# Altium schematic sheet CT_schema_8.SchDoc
size 252 x 159 mm
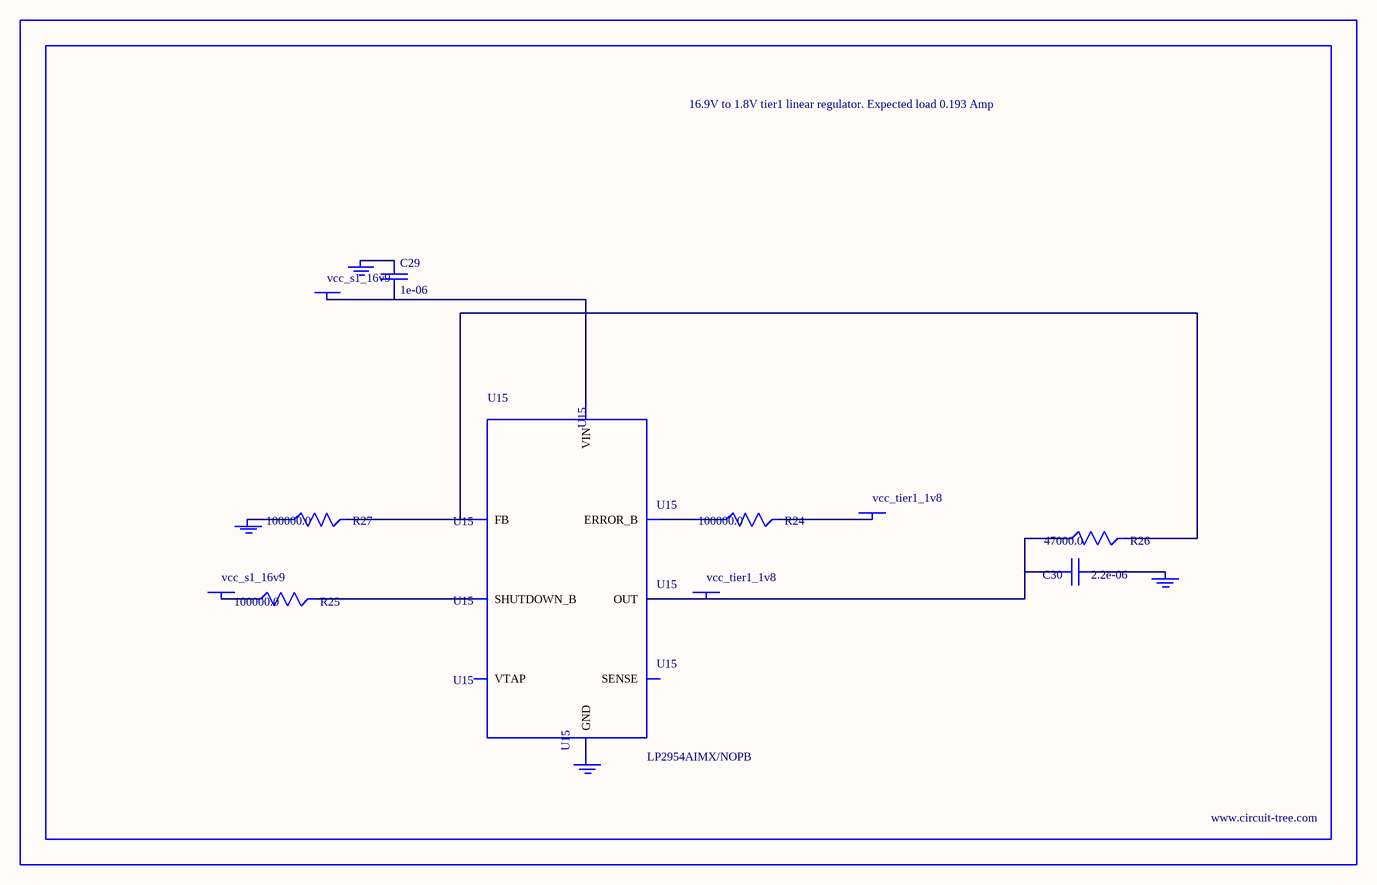
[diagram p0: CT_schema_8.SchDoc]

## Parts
BORDER7  (no value)
C29  1e-06  [EXV-9B]
C30  2.2e-06  [EXV-9B]
GND_INSTANCE_7_0  (no value)
GND_INSTANCE_7_1  (no value)
GND_INSTANCE_7_2  (no value)
GND_INSTANCE_7_3  (no value)
POWER_INSTANCE_7_0  vcc_s1_16v9
POWER_INSTANCE_7_1  vcc_tier1_1v8
POWER_INSTANCE_7_2  vcc_s1_16v9
POWER_INSTANCE_7_3  vcc_tier1_1v8
R24  100000.0  [R0603]
R25  100000.0  [R0603]
R26  47000.0  [R0603]
R27  100000.0  [R0603]
U15  LP2954AIMX/NOPB  [LP2954]

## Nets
NetC29_1: C29.1 GND_INSTANCE_7_2.0(GND)
NetC29_2: C29.2 POWER_INSTANCE_7_2.0(PWR) U15.8(VIN)
NetC30_1: C30.1 GND_INSTANCE_7_0.0(GND)
NetC30_2: C30.2 POWER_INSTANCE_7_3.0(PWR) R26.1 U15.1(OUT)
NetGND_INSTANCE_7_1_0: GND_INSTANCE_7_1.0(GND) R27.1
NetGND_INSTANCE_7_3_0: GND_INSTANCE_7_3.0(GND) U15.4(GND)
NetPOWER_INSTANCE_7_0_0: POWER_INSTANCE_7_0.0(PWR) R25.1
NetPOWER_INSTANCE_7_1_0: POWER_INSTANCE_7_1.0(PWR) R24.2
NetR24_1: R24.1 U15.5(ERROR_B)
NetR25_2: R25.2 U15.3(SHUTDOWN_B)
NetR26_2: R26.2 R27.2 U15.7(FB)

Not connected (* = marked no-connect by the designer): U15 2(SENSE) 6(VTAP)

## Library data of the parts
BORDER7 = BORDER_PAGE7
C29 = EDK105M050A9BAA
C30 = EDK225M050A9BAA
GND_INSTANCE_7_0-GND_INSTANCE_7_3 = GND
POWER_INSTANCE_7_0-POWER_INSTANCE_7_3 = PWR
R24 R25 R27 = RC0603JR-07100KL
R26 = RC0603JR-0747KL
